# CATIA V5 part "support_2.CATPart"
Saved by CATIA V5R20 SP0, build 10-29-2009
Part number: support_2
Publications: "support2_barre", "support2_pivotcent", "support2_pivotext", "support2_pivotint"
Bounding box of the stored display mesh (mm): x -10 to 10, y -50 to 350, z 0 to 0
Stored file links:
  C:\Users\Noëllie\Documents\IFMA\2A\S3\IAO\Projet Artobolevski\Catia\support_2.CATPart
  C:\Users\Noëllie\Documents\IFMA\2A\S3\IAO\Projet Artobolevski\Catia\Artobolevski 782.CATProduct
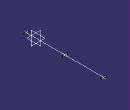
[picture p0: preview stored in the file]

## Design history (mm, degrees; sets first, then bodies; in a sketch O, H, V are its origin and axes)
Set1
  Point1 "B2g": linked copy from another document
  Point2 "B2d": linked copy from another document
  Point3 "A2": linked copy from another document
Body1 (main body)
  Line1 "support2_barre": type PtPt, FirstPoint Point1, SecondPoint Point2
  Line2 "support2_pivotcent": type PtDir, RefPoint Point3, Direction yz-plane, Start 10, End -10
  Line3 "support2_pivotext": type PtDir, RefPoint Point2, Direction yz-plane, Start 10, End -10
  Line4 "support2_pivotint": type PtDir, RefPoint Point1, Direction yz-plane, Start 10, End -10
